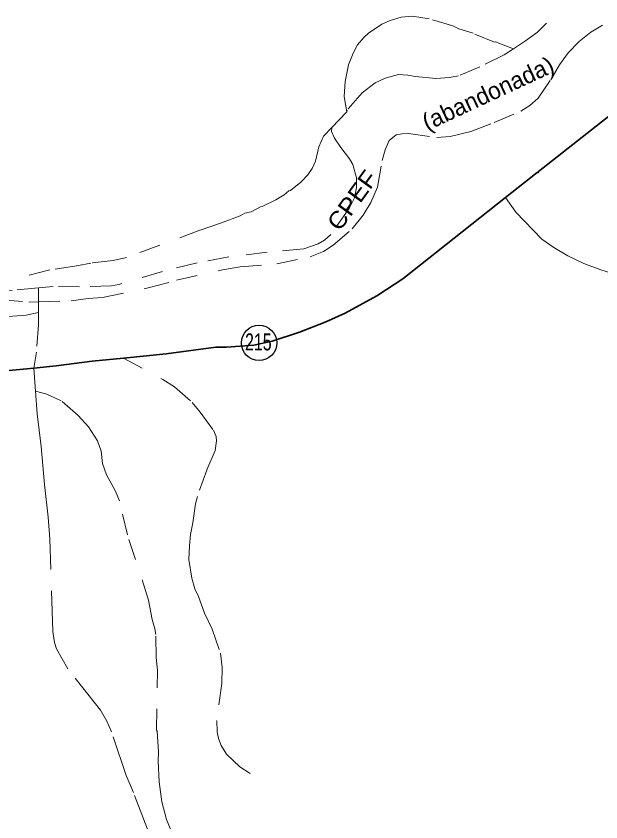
# Model space of a CAD drawing. Extents: x 783.4 to 809.8, y 7536.4 to 7564.6.
# Drawn here: x 795.406 to 798.152, y 7553.23 to 7557.018 of the extents above; entities that cross this region are included whole.
import ezdxf
from ezdxf.enums import TextEntityAlignment as Align

# ---------------------------------------------------------------- set-up
doc = ezdxf.new("R2010")
doc.units = 0
doc.header["$LTSCALE"] = 0.032
doc.linetypes.add('DOTTED', pattern=[1.5, 0.3, -1.2])
doc.linetypes.add('LONG_DASHED', pattern=[7.5, 6, -1.5])
for name, color, linetype, lineweight in [('13', 7, 'Continuous', 25), ('18', 7, 'DOTTED', 13), ('2', 7, 'Continuous', 35), ('5', 7, 'LONG_DASHED', 13), ('7', 7, 'DOTTED', 13)]:
    doc.layers.add(name, color=color, linetype=linetype, lineweight=lineweight)
doc.layers.add('61', color=7, linetype='Continuous')

msp = doc.modelspace()

# ---------------------------------------------------------------- linework, layer by layer
at = {"layer": '13'}
msp.add_circle((796.5471, 7555.482), 0.083, dxfattribs=at)
at = {"layer": '18'}
for points in [[(795.5114, 7555.6747), (795.6641, 7555.679), (795.7446, 7555.6902), (795.8122, 7555.6954), (796.0267, 7555.7405), (796.159, 7555.7762), (796.375, 7555.8246), (796.4581, 7555.8396), (796.63, 7555.8533), (796.7874, 7555.8862), (796.8495, 7555.9116), (796.8946, 7555.9407), (796.9848, 7556.0187), (797.0354, 7556.0831), (797.0725, 7556.1413), (797.1026, 7556.2146), (797.1256, 7556.3396), (797.1391, 7556.3899), (797.1582, 7556.4331), (797.1902, 7556.4594), (797.2183, 7556.4651), (797.2484, 7556.466), (797.3817, 7556.4481), (797.4448, 7556.4528), (797.541, 7556.4763), (797.6517, 7556.5181), (797.776, 7556.5707), (797.8181, 7556.598), (797.8572, 7556.6328), (797.9173, 7556.7192), (797.9574, 7556.7888), (797.998, 7556.8457), (798.0501, 7556.8992), (798.1052, 7556.9424), (798.1603, 7556.9753)], [(795.3371, 7555.685), (795.4657, 7555.6734), (795.5114, 7555.6747)]]:
    msp.add_lwpolyline(points, dxfattribs=at)
at = {"layer": '2'}
for points in [[(797.7039, 7556.1648), (797.8531, 7556.2828), (797.8571, 7556.2828), (797.8587, 7556.2876), (798.4312, 7556.7372)], [(795.9099, 7555.4106), (796.1101, 7555.4311), (796.3435, 7555.4611), (796.3947, 7555.4619), (796.5216, 7555.472), (796.6088, 7555.4908), (796.7371, 7555.5331), (796.8571, 7555.5795), (796.9515, 7555.6219), (797.1003, 7555.7035), (797.2219, 7555.7835), (797.7039, 7556.1648)], [(795.4886, 7555.3627), (795.5947, 7555.3739), (795.7627, 7555.3955), (795.9099, 7555.4106)], [(793.6797, 7555.1787), (794.9319, 7555.3091), (795.2716, 7555.3423), (795.4886, 7555.3627)]]:
    msp.add_lwpolyline(points, dxfattribs=at)
at = {"layer": '5'}
msp.add_line((795.4964, 7555.2546), (795.4886, 7555.3627), dxfattribs=at)
for points in [[(798.2476, 7555.7963), (798.1516, 7555.8251), (798.0716, 7555.8555), (797.9972, 7555.8907), (797.9316, 7555.9306), (797.8754, 7555.9701), (797.7532, 7556.096), (797.7039, 7556.1648)], [(796.0772, 7553.0434), (796.0595, 7553.0882), (796.0307, 7553.1754), (795.957, 7553.3685), (795.9235, 7553.4482), (795.8547, 7553.6531), (795.8323, 7553.7043), (795.8019, 7553.7555), (795.6491, 7553.9499), (795.5959, 7554.0443), (795.5867, 7554.0739), (795.5779, 7554.1251), (795.5651, 7554.5603), (795.5571, 7554.6627), (795.5387, 7554.8163), (795.5243, 7554.9955), (795.5051, 7555.1491), (795.4964, 7555.2546)]]:
    msp.add_lwpolyline(points, dxfattribs=at)
at = {"layer": '7'}
msp.add_line((795.5114, 7555.6747), (795.5115, 7555.6254), dxfattribs=at)
for points in [[(797.7417, 7556.8645), (797.6576, 7556.8976), (797.6531, 7556.8956), (797.5523, 7556.9372), (797.4851, 7556.9588), (797.4563, 7556.9716), (797.3459, 7557.0052), (797.2675, 7557.018), (797.2139, 7557.0132), (797.1627, 7556.998), (797.1235, 7556.9804), (797.0611, 7556.9372), (797.0395, 7556.9172), (797.0099, 7556.8828), (796.9883, 7556.8436), (796.9675, 7556.7892), (796.9515, 7556.7108), (796.9467, 7556.6404), (796.9584, 7556.5676)], [(797.897, 7556.9848), (797.854, 7556.9432), (797.7988, 7556.9022), (797.7417, 7556.8645)], [(797.7417, 7556.8645), (797.6979, 7556.8356), (797.5835, 7556.7796), (797.4835, 7556.7372), (797.4411, 7556.7292), (797.3771, 7556.7252), (797.2811, 7556.7348), (797.2451, 7556.7412), (797.2011, 7556.7428), (797.1387, 7556.726), (797.0915, 7556.7044), (797.0307, 7556.6572), (796.9611, 7556.5764), (796.9584, 7556.5676)], [(796.9584, 7556.5676), (796.9579, 7556.566), (796.8889, 7556.4939)], [(796.8889, 7556.4939), (796.8499, 7556.4532), (796.8283, 7556.4036), (796.8123, 7556.3364), (796.7963, 7556.302), (796.7755, 7556.2724), (796.7427, 7556.238), (796.6939, 7556.1979), (796.6875, 7556.1963), (796.6651, 7556.1779), (796.6259, 7556.1539), (796.5619, 7556.1227), (796.5531, 7556.1211), (796.5091, 7556.0987), (796.4803, 7556.0915), (796.4579, 7556.0795), (796.3659, 7556.0443), (796.2683, 7556.0115), (795.9243, 7555.8827), (795.8619, 7555.8699), (795.7563, 7555.8571), (795.6891, 7555.8435), (795.5643, 7555.8251), (795.3395, 7555.7675)], [(796.8889, 7556.4939), (796.8876, 7556.475), (796.9019, 7556.4437), (796.9306, 7556.4011), (796.9723, 7556.3476), (796.9867, 7556.3204), (797.0048, 7556.2576), (797.0041, 7556.2125), (796.9945, 7556.1632), (796.9708, 7556.1133), (796.8835, 7555.9918), (796.8539, 7555.9641), (796.825, 7555.9481), (796.757, 7555.9246), (796.5857, 7555.9082), (796.4052, 7555.8867), (796.2568, 7555.8586), (796.0933, 7555.8183), (795.888, 7555.7563), (795.8539, 7555.75), (795.7045, 7555.7459), (795.5798, 7555.7476), (795.5113, 7555.7409), (795.5114, 7555.6747)], [(795.5113, 7555.7409), (795.3882, 7555.7289), (795.3264, 7555.7306), (795.2828, 7555.7355), (795.1429, 7555.7646), (795.0602, 7555.7755), (794.9594, 7555.8059), (794.8601, 7555.8278), (794.6203, 7555.893), (794.5393, 7555.9107), (794.4586, 7555.9239), (794.3721, 7555.9454), (794.307, 7555.9572), (794.226, 7555.9784), (794.169, 7556.0006), (794.1539, 7556.0272), (794.1436, 7556.0688), (794.1103, 7556.2506), (794.0988, 7556.2877), (794.0924, 7556.2992)], [(795.5115, 7555.6254), (795.4536, 7555.6118), (795.3681, 7555.6064), (795.3116, 7555.6118), (794.4159, 7555.8292), (794.1927, 7555.8727), (793.9673, 7555.9333), (793.88, 7555.958), (793.8195, 7555.972)], [(795.5115, 7555.6254), (795.5116, 7555.567), (795.502, 7555.4388), (795.4886, 7555.3627)], [(795.9099, 7555.4106), (796.0955, 7555.3099), (796.1491, 7555.2747), (796.2331, 7555.2019), (796.2707, 7555.1563), (796.3325, 7555.0716), (796.3458, 7555.0417), (796.3466, 7555.0223), (796.3414, 7554.9765), (796.3019, 7554.8835), (796.2571, 7554.7603), (796.2491, 7554.7259), (796.2363, 7554.6363), (796.2251, 7554.5811), (796.2195, 7554.5283), (796.2171, 7554.4635), (796.2315, 7554.3755), (796.2451, 7554.3251), (796.2619, 7554.2891), (796.2915, 7554.2107), (796.3267, 7554.1355), (796.3653, 7554.0231), (796.3739, 7553.9555), (796.3715, 7553.8803), (796.3483, 7553.7067), (796.3507, 7553.6531), (796.3571, 7553.6219), (796.3691, 7553.5891), (796.3939, 7553.5483), (796.4562, 7553.4891), (796.5047, 7553.4583)], [(796.1395, 7553.1778), (796.1123, 7553.241), (796.0899, 7553.325), (796.0779, 7553.4186), (796.0731, 7553.5154), (796.0747, 7553.5603), (796.0683, 7553.6563), (796.0651, 7553.6611), (796.0707, 7553.942), (796.0645, 7554.0027), (796.0616, 7554.1106), (796.0579, 7554.1376), (796.0446, 7554.1813), (796.0283, 7554.2729), (795.9291, 7554.5795), (795.8915, 7554.7395), (795.8707, 7554.7883), (795.8299, 7554.8619), (795.8123, 7554.9155), (795.8051, 7554.9731), (795.7883, 7555.0219), (795.7467, 7555.0867), (795.6979, 7555.1411), (795.6179, 7555.2091), (795.5507, 7555.2411), (795.4964, 7555.2546)]]:
    msp.add_lwpolyline(points, dxfattribs=at)

# ---------------------------------------------------------------- texts
at = {"layer": '61'}
msp.add_text('(abandonada)', height=0.08, rotation=25, dxfattribs=at).set_placement((797.6387, 7556.6184), align=Align.CENTER)
at = {"layer": '61', "width": 1.1}
msp.add_text('CPEF', height=0.08, rotation=54, dxfattribs=at).set_placement((797.0175, 7556.1291), align=Align.CENTER)
at = {"layer": '61', "width": 0.7}
msp.add_text('215', height=0.08, dxfattribs=at).set_placement((796.5435, 7555.4466), align=Align.CENTER)

doc.saveas('drawing.dxf')
